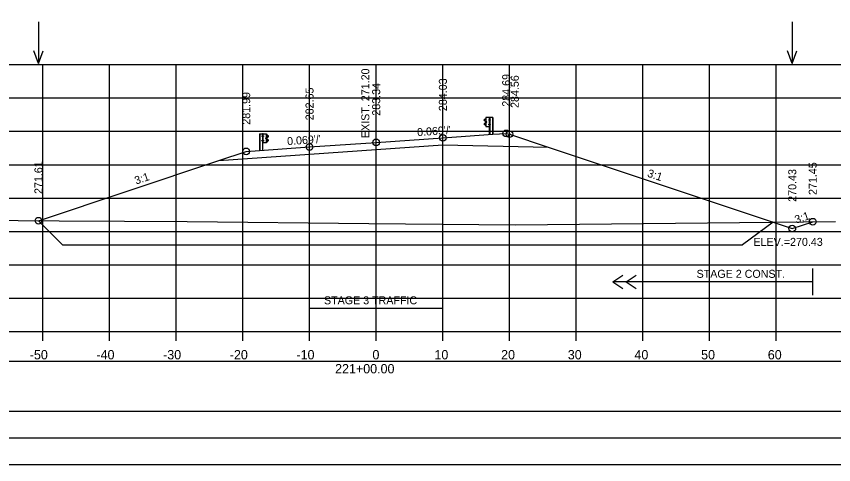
# Model space of a CAD drawing. Extents: x 4667 to 1632277, y -2100 to 724501.
# Drawn here: x 5723.2 to 5845.8, y -683.7 to -616.5 of the extents above; entities that cross this region are included whole.
import ezdxf

# ---------------------------------------------------------------- set-up
doc = ezdxf.new("R2010")
doc.units = 0
for name, color, linetype in [('R_Alt Surface', 7, 'Continuous'), ('R_Axis', 7, 'Continuous'), ('R_Axis Annot', 7, 'Continuous'), ('R_Border', 7, 'Continuous'), ('R_Draft', 7, 'Continuous'), ('R_Exist Surface', 7, 'Continuous'), ('R_Fin Surface', 7, 'Continuous'), ('R_Fin Surface Annot', 7, 'Continuous'), ('R_Grid', 7, 'Continuous'), ('R_No Plot', 7, 'Continuous'), ('R_Proposed CofA', 7, 'Continuous'), ('R_ROW', 7, 'Continuous'), ('R_Temp Easement', 7, 'Continuous'), ('R_Water Annot', 7, 'Continuous')]:
    doc.layers.add(name, color=color, linetype=linetype)

msp = doc.modelspace()

# ---------------------------------------------------------------- linework, layer by layer
at = {"layer": 'R_Alt Surface'}
msp.add_lwpolyline([(5753.58, -638.13), (5767.18, -637.19), (5777.18, -636.5), (5787.18, -635.8), (5802.98, -636.12)], dxfattribs=at)
at = {"layer": 'R_Axis'}
for p, q in [((5667.18, -663.75), (5947.18, -663.75)), ((5727.18, -665.15), (5727.18, -663.75)), ((5737.18, -665.15), (5737.18, -663.75)), ((5747.18, -665.15), (5747.18, -663.75)), ((5757.18, -665.15), (5757.18, -663.75)), ((5767.18, -665.15), (5767.18, -663.75)), ((5777.18, -665.15), (5777.18, -663.75)), ((5787.18, -665.15), (5787.18, -663.75)), ((5797.18, -665.15), (5797.18, -663.75)), ((5807.18, -665.15), (5807.18, -663.75)), ((5817.18, -665.15), (5817.18, -663.75)), ((5827.18, -665.15), (5827.18, -663.75)), ((5837.18, -665.15), (5837.18, -663.75))]:
    msp.add_line(p, q, dxfattribs=at)
at = {"layer": 'R_Border'}
msp.add_line((5964.36, -679.75), (5648.18, -679.75), dxfattribs=at)
at = {"layer": 'R_Draft'}
for p, q in [((5793.39, -632.01), (5793.52, -631.9)), ((5793.56, -632.25), (5793.39, -632.15)), ((5793.4, -632.02), (5793.53, -631.92)), ((5793.57, -632.23), (5793.4, -632.13)), ((5793.41, -632.59), (5793.57, -632.49)), ((5793.42, -632.61), (5793.58, -632.51)), ((5793.52, -631.9), (5793.63, -631.84)), ((5793.53, -631.92), (5793.62, -631.87)), ((5793.6, -632.43), (5793.6, -632.3)), ((5793.62, -632.43), (5793.62, -632.3)), ((5793.66, -633.05), (5793.66, -631.69)), ((5793.67, -632.43), (5793.67, -632.31)), ((5793.67, -632.31), (5793.72, -632.31)), ((5793.67, -632.34), (5793.72, -632.34)), ((5793.67, -632.4), (5793.72, -632.4)), ((5793.67, -632.4), (5793.72, -632.4)), ((5793.67, -632.43), (5793.72, -632.43)), ((5793.73, -632.42), (5793.73, -632.32)), ((5794.15, -631.99), (5794.1, -631.99)), ((5794.1, -631.99), (5794.1, -632.12)), ((5794.1, -632.06), (5794.16, -632.06)), ((5794.15, -632.12), (5794.1, -632.12)), ((5794.16, -631.69), (5794.17, -631.69)), ((5794.16, -631.69), (5794.23, -631.69)), ((5794.19, -634.2), (5794.19, -631.69)), ((5794.23, -632.11), (5794.23, -631.99)), ((5794.23, -631.99), (5794.28, -631.99)), ((5794.23, -632.02), (5794.28, -632.02)), ((5794.23, -632.08), (5794.27, -632.08)), ((5794.23, -632.08), (5794.28, -632.08)), ((5794.23, -632.11), (5794.28, -632.11)), ((5794.28, -632.1), (5794.28, -632)), ((5794.65, -631.69), (5794.65, -634.2)), ((5794.68, -631.69), (5794.68, -634.2)), ((5793.51, -632.85), (5793.38, -632.74)), ((5793.52, -632.84), (5793.4, -632.73)), ((5793.62, -632.91), (5793.51, -632.85)), ((5793.63, -632.89), (5793.52, -632.84)), ((5794.1, -632.8), (5794.1, -632.68)), ((5794.1, -632.68), (5794.15, -632.68)), ((5794.1, -632.74), (5794.16, -632.74)), ((5794.1, -632.8), (5794.15, -632.8)), ((5794.16, -633.05), (5794.19, -633.05)), ((5794.24, -632.8), (5794.24, -632.68)), ((5794.24, -632.68), (5794.29, -632.68)), ((5794.24, -632.71), (5794.29, -632.71)), ((5794.24, -632.77), (5794.28, -632.77)), ((5794.24, -632.77), (5794.29, -632.77)), ((5794.24, -632.8), (5794.29, -632.8)), ((5794.29, -632.79), (5794.29, -632.69)), ((5759.68, -634.11), (5759.68, -636.62)), ((5759.71, -634.11), (5759.71, -636.62)), ((5760.08, -634.52), (5760.08, -634.42)), ((5760.14, -634.41), (5760.09, -634.41)), ((5760.14, -634.44), (5760.09, -634.44)), ((5760.14, -634.5), (5760.09, -634.5)), ((5760.14, -634.53), (5760.09, -634.53)), ((5760.14, -634.5), (5760.1, -634.5)), ((5760.21, -634.11), (5760.14, -634.11)), ((5760.14, -634.53), (5760.14, -634.41)), ((5760.18, -636.62), (5760.18, -634.11)), ((5760.21, -634.11), (5760.2, -634.11)), ((5760.26, -634.48), (5760.21, -634.48)), ((5760.22, -634.41), (5760.27, -634.41)), ((5760.22, -634.54), (5760.27, -634.54)), ((5760.27, -634.41), (5760.27, -634.54)), ((5760.64, -634.84), (5760.64, -634.74)), ((5760.7, -634.73), (5760.65, -634.73)), ((5760.7, -634.76), (5760.65, -634.76)), ((5760.7, -634.82), (5760.65, -634.82)), ((5760.7, -634.82), (5760.65, -634.82)), ((5760.7, -634.85), (5760.65, -634.85)), ((5760.7, -634.85), (5760.7, -634.73)), ((5760.71, -635.47), (5760.71, -634.11)), ((5760.85, -634.32), (5760.74, -634.26)), ((5760.84, -634.34), (5760.75, -634.29)), ((5760.75, -634.85), (5760.75, -634.72)), ((5760.77, -634.85), (5760.77, -634.72)), ((5760.79, -634.65), (5760.97, -634.55)), ((5760.94, -635.03), (5760.79, -634.93)), ((5760.96, -635.01), (5760.8, -634.91)), ((5760.81, -634.67), (5760.98, -634.57)), ((5760.97, -634.44), (5760.84, -634.34)), ((5760.98, -634.43), (5760.85, -634.32)), ((5760.07, -635.21), (5760.07, -635.11)), ((5760.13, -635.1), (5760.08, -635.1)), ((5760.13, -635.13), (5760.08, -635.13)), ((5760.13, -635.19), (5760.08, -635.19)), ((5760.13, -635.22), (5760.08, -635.22)), ((5760.13, -635.19), (5760.09, -635.19)), ((5760.13, -635.22), (5760.13, -635.1)), ((5760.21, -635.47), (5760.17, -635.47)), ((5760.26, -635.16), (5760.21, -635.16)), ((5760.27, -635.1), (5760.22, -635.1)), ((5760.27, -635.22), (5760.22, -635.22)), ((5760.27, -635.22), (5760.27, -635.1)), ((5760.74, -635.31), (5760.84, -635.26)), ((5760.74, -635.33), (5760.86, -635.27)), ((5760.84, -635.26), (5760.97, -635.15)), ((5760.86, -635.27), (5760.98, -635.16))]:
    msp.add_line(p, q, dxfattribs=at)
for points in [[(5793.63, -631.69), (5793.64, -633.05), (5794.16, -633.05), (5794.16, -631.69)], [(5793.67, -632.29), (5793.67, -632.46), (5793.66, -632.46), (5793.66, -632.29)], [(5793.73, -632.34), (5793.73, -632.4), (5793.76, -632.4), (5793.76, -632.34)], [(5794.1, -631.99), (5794.1, -632.12), (5794.16, -632.12), (5794.16, -631.99)], [(5794.23, -631.97), (5794.23, -632.14), (5794.22, -632.14), (5794.22, -631.97)], [(5794.29, -632.02), (5794.29, -632.08), (5794.31, -632.08), (5794.31, -632.02)], [(5794.1, -632.68), (5794.1, -632.8), (5794.16, -632.8), (5794.16, -632.68)], [(5794.24, -632.66), (5794.24, -632.83), (5794.23, -632.83), (5794.23, -632.66)], [(5794.3, -632.71), (5794.3, -632.77), (5794.32, -632.77), (5794.32, -632.71)], [(5760.08, -634.44), (5760.08, -634.5), (5760.06, -634.5), (5760.06, -634.44)], [(5760.14, -634.39), (5760.14, -634.56), (5760.15, -634.56), (5760.15, -634.39)], [(5760.73, -634.11), (5760.73, -635.47), (5760.21, -635.47), (5760.21, -634.11)], [(5760.26, -634.41), (5760.26, -634.54), (5760.21, -634.54), (5760.21, -634.41)], [(5760.64, -634.76), (5760.64, -634.82), (5760.61, -634.82), (5760.61, -634.76)], [(5760.69, -634.71), (5760.69, -634.88), (5760.7, -634.88), (5760.7, -634.71)], [(5760.07, -635.13), (5760.07, -635.19), (5760.05, -635.19), (5760.05, -635.13)], [(5760.13, -635.08), (5760.13, -635.25), (5760.14, -635.25), (5760.14, -635.08)], [(5760.26, -635.1), (5760.26, -635.22), (5760.21, -635.22), (5760.21, -635.1)]]:
    msp.add_lwpolyline(points, close=True, dxfattribs=at)
for points in [[(5794.68, -631.69), (5794.23, -631.69), (5794.23, -634.2)], [(5759.68, -634.11), (5760.14, -634.11), (5760.14, -636.62)]]:
    msp.add_lwpolyline(points, dxfattribs=at)
for centre, radius, start, end in [((5793.43, -632.07), 0.0856, 122.0217, 240.7501), ((5793.43, -632.07), 0.062, 122.0217, 240.7501), ((5793.53, -632.31), 0.0622, 4.9556, 61.894), ((5793.6, -632.38), 0.0453, 93.9303, 257.0446), ((5793.53, -632.31), 0.0865, 4.9556, 61.894), ((5793.55, -632.44), 0.0462, 293.1464, 8.2196), ((5793.55, -632.44), 0.0703, 293.1464, 8.2196), ((5793.71, -632.33), 0.022, 317.7756, 45.4255), ((5793.64, -632.37), 0.0922, 339.7423, 20.2577), ((5793.7, -632.42), 0.025, 323.3766, 39.0666), ((5794.26, -632), 0.022, 317.7756, 45.4255), ((5794.19, -632.05), 0.0922, 339.7423, 20.2577), ((5794.26, -632.1), 0.025, 323.3766, 39.0666), ((5793.47, -632.68), 0.109, 120.88, 214.7816), ((5793.47, -632.68), 0.0854, 120.88, 214.7816), ((5794.27, -632.69), 0.022, 317.7756, 45.4255), ((5794.2, -632.74), 0.0922, 339.7423, 20.2577), ((5794.27, -632.79), 0.025, 323.3766, 39.0666), ((5760.11, -634.42), 0.022, 134.5745, 222.2244), ((5760.18, -634.47), 0.0922, 159.7423, 200.2577), ((5760.11, -634.52), 0.025, 140.9334, 216.6234), ((5760.66, -634.75), 0.022, 134.5745, 222.2244), ((5760.73, -634.79), 0.0922, 159.7423, 200.2577), ((5760.67, -634.84), 0.025, 140.9334, 216.6234), ((5760.84, -634.73), 0.0865, 118.106, 175.0444), ((5760.82, -634.86), 0.0703, 171.7804, 246.8536), ((5760.84, -634.73), 0.0622, 118.106, 175.0444), ((5760.77, -634.8), 0.0453, 282.9554, 86.0697), ((5760.82, -634.86), 0.0462, 171.7804, 246.8536), ((5760.9, -635.1), 0.0854, 325.2184, 59.12), ((5760.9, -635.1), 0.109, 325.2184, 59.12), ((5760.94, -634.49), 0.062, 299.2499, 57.9783), ((5760.94, -634.49), 0.0856, 299.2499, 57.9783), ((5760.1, -635.11), 0.022, 134.5745, 222.2244), ((5760.17, -635.16), 0.0922, 159.7423, 200.2577), ((5760.1, -635.21), 0.025, 140.9334, 216.6234)]:
    msp.add_arc(centre, radius, start, end, dxfattribs=at)
at = {"layer": 'R_Exist Surface'}
msp.add_lwpolyline([(5667.18, -646.62), (5677.62, -646.71), (5690.13, -646.83), (5701.21, -646.93), (5711.1, -647.02), (5729.62, -647.18), (5739.45, -647.22), (5748.81, -647.25), (5776.06, -647.55), (5798.09, -647.78), (5846.08, -647.27)], dxfattribs=at)
at = {"layer": 'R_Fin Surface'}
msp.add_lwpolyline([(5726.52, -647.15), (5753.58, -638.13), (5757.68, -636.76), (5759.68, -636.62), (5767.18, -636.1), (5777.18, -635.41), (5787.18, -634.72), (5794.68, -634.2), (5796.68, -634.06), (5797.18, -634.19), (5802.98, -636.12), (5839.59, -648.32), (5842.66, -647.3)], dxfattribs=at)
at = {"layer": 'R_Grid'}
for p, q in [((5667.18, -623.75), (5947.18, -623.75)), ((5727.18, -663.75), (5727.18, -623.75)), ((5737.18, -663.75), (5737.18, -623.75)), ((5747.18, -663.75), (5747.18, -623.75)), ((5757.18, -663.75), (5757.18, -623.75)), ((5767.18, -663.75), (5767.18, -623.75)), ((5777.18, -663.75), (5777.18, -623.75)), ((5787.18, -663.75), (5787.18, -623.75)), ((5797.18, -663.75), (5797.18, -623.75)), ((5807.18, -663.75), (5807.18, -623.75)), ((5817.18, -663.75), (5817.18, -623.75)), ((5827.18, -663.75), (5827.18, -623.75)), ((5837.18, -663.75), (5837.18, -623.75)), ((5667.18, -628.75), (5947.18, -628.75)), ((5667.18, -633.75), (5947.18, -633.75)), ((5667.18, -638.75), (5947.18, -638.75)), ((5667.18, -643.75), (5947.18, -643.75)), ((5667.18, -648.75), (5947.18, -648.75)), ((5667.18, -653.75), (5947.18, -653.75)), ((5667.18, -658.75), (5947.18, -658.75)), ((5667.18, -663.75), (5947.18, -663.75))]:
    msp.add_line(p, q, dxfattribs=at)
at = {"layer": 'R_No Plot'}
msp.add_line((5635.78, -683.73), (5969.12, -683.73), dxfattribs=at)
for points in [[(5635.78, -470.4), (5969.12, -470.4), (5969.12, -683.74), (5635.78, -683.74)], [(5882.1, -474.29), (5901.72, -474.29), (5901.72, -484.17), (5917.84, -484.17), (5941.04, -484.17), (5941.04, -508.51), (5964.36, -508.51), (5964.36, -679.75), (5648.18, -679.75), (5648.18, -474.29)]]:
    msp.add_lwpolyline(points, close=True, dxfattribs=at)
for centre in [(5796.68, -634.06), (5797.18, -634.19), (5777.18, -635.41), (5787.18, -634.72), (5767.18, -636.1), (5757.68, -636.76), (5757.68, -636.76), (5726.52, -647.15), (5842.66, -647.3), (5839.59, -648.32)]:
    msp.add_circle(centre, 0.5, dxfattribs=at)
at = {"layer": 'R_Proposed CofA'}
for p, q in [((5812.66, -656.3), (5814.16, -655.3)), ((5814.66, -656.3), (5816.16, -655.3)), ((5812.66, -656.3), (5814.16, -657.3)), ((5814.66, -656.3), (5816.16, -657.3))]:
    msp.add_line(p, q, dxfattribs=at)
msp.add_lwpolyline([(5667.23, -675.7), (5947.13, -675.7), (5947.13, -668.28), (5667.23, -668.28)], close=True, dxfattribs=at)
at = {"layer": 'R_ROW'}
for p, q in [((5726.52, -647.15), (5730.15, -650.78)), ((5836.71, -647.37), (5832.13, -650.78)), ((5730.15, -650.78), (5832.13, -650.78))]:
    msp.add_line(p, q, dxfattribs=at)
at = {"layer": 'R_Temp Easement'}
for p, q in [((5842.66, -658.3), (5842.66, -654.3)), ((5842.66, -656.3), (5812.66, -656.3)), ((5767.18, -662.3), (5767.18, -658.3)), ((5787.18, -662.3), (5787.18, -658.3)), ((5787.18, -660.3), (5767.18, -660.3))]:
    msp.add_line(p, q, dxfattribs=at)
at = {"layer": 'R_Water Annot'}
for p, q in [((5726.52, -617.32), (5726.52, -623.6)), ((5839.59, -617.32), (5839.59, -623.6)), ((5726.52, -623.6), (5725.82, -621.68)), ((5726.52, -623.6), (5727.22, -621.68)), ((5839.59, -623.6), (5838.89, -621.68)), ((5839.59, -623.6), (5840.29, -621.68))]:
    msp.add_line(p, q, dxfattribs=at)

# ---------------------------------------------------------------- texts
at = {"layer": 'R_Axis Annot'}
for s, p in [('-50', (5725.22, -667.95)), ('-40', (5735.22, -667.95)), ('-30', (5745.22, -667.95)), ('-20', (5755.22, -667.95)), ('-10', (5765.22, -667.95)), ('0', (5776.62, -667.95)), ('10', (5785.92, -667.95)), ('20', (5795.92, -667.95)), ('30', (5805.92, -667.95)), ('40', (5815.92, -667.95)), ('50', (5825.92, -667.95)), ('60', (5835.92, -667.95)), ('221+00.00', (5771.02, -670.05))]:
    msp.add_text(s, height=1.4, dxfattribs=at).set_placement(p)
at = {"layer": 'R_Fin Surface Annot'}
for s, rotation, p in [('284.03', 90, (5787.78, -630.72)), ('284.69', 90, (5797.28, -630.06)), ('284.56', 90, (5798.57, -630.25)), ('282.65', 90, (5767.78, -632.1)), ('283.34', 90, (5777.78, -631.41)), ('281.99', 90, (5758.28, -632.76)), ("0.069'/'", 3.9551, (5783.36, -634.48)), ("0.069'/'", 3.9551, (5763.86, -635.83)), ('271.61', 90, (5727.12, -643.15)), ('271.45', 90, (5843.26, -643.3)), ('3:1', 341.5651, (5817.76, -640.52)), ('270.43', 90, (5840.19, -644.32)), ('3:1', 18.4349, (5741.16, -641.74)), ('3:1', 18.4349, (5840.18, -647.6))]:
    msp.add_text(s, height=1.2, rotation=rotation, dxfattribs=at).set_placement(p)
at = {"layer": 'R_Temp Easement'}
msp.add_text('EXIST. 271.20', height=1.2, rotation=90, dxfattribs=at).set_placement((5776.15, -634.76))
for s, p in [('STAGE 2 CONST.', (5825.24, -655.72)), ('STAGE 3 TRAFFIC', (5769.35, -659.69))]:
    msp.add_text(s, height=1.1985, dxfattribs=at).set_placement(p)
at = {"layer": 'R_Water Annot'}
msp.add_text('ELEV.=270.43', height=1.2, dxfattribs=at).set_placement((5833.77, -650.93))

doc.saveas('drawing.dxf')
